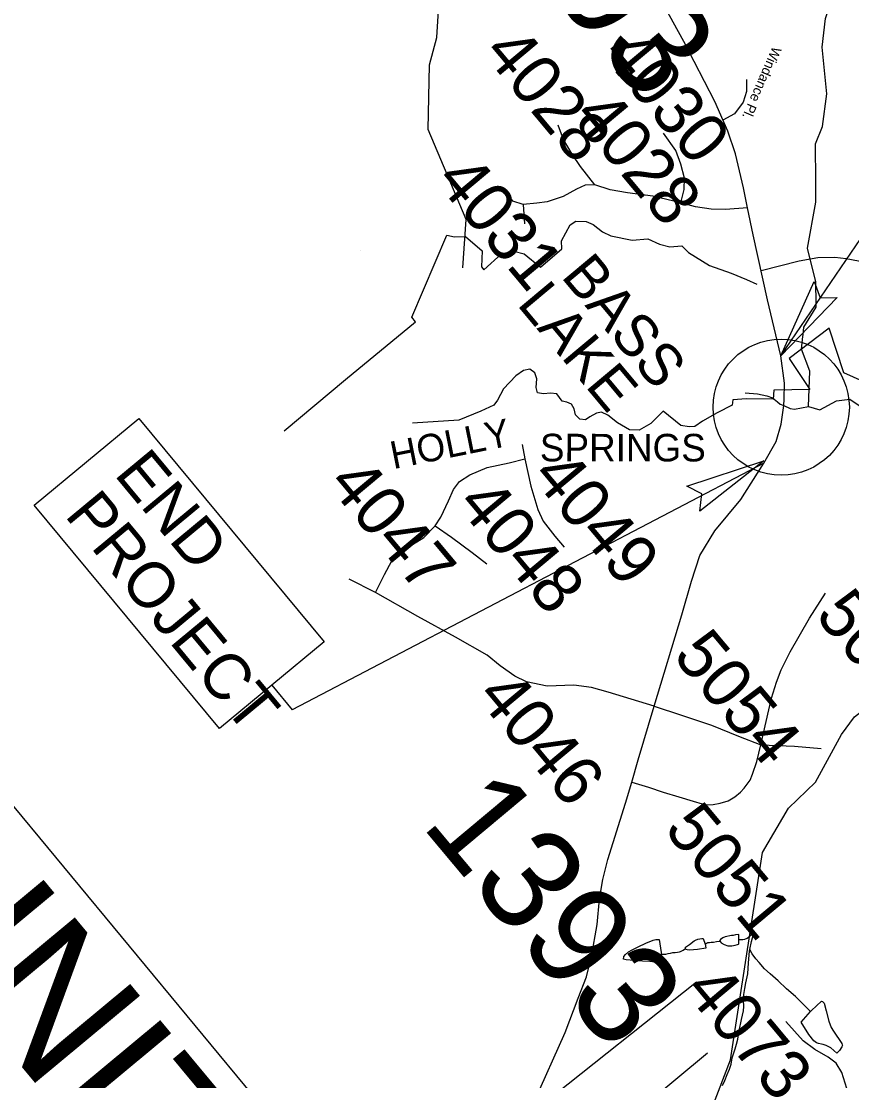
# Model space of a CAD drawing. Extents: x 2054826 to 2060231, y 685508 to 690809.
# Drawn here: x 2058521.5 to 2058702.3, y 689444.4 to 689675 of the extents above; entities that cross this region are included whole.
import ezdxf

# ---------------------------------------------------------------- set-up
doc = ezdxf.new("R2010")
doc.units = 0
for name, color, linetype in [('Old_Level_10', 7, 'Continuous'), ('Old_Level_11', 7, 'Continuous'), ('Old_Level_19', 7, 'Continuous'), ('Old_Level_21', 7, 'Continuous'), ('Old_Level_32', 7, 'Continuous'), ('Old_Level_35', 7, 'Continuous'), ('Old_Level_48', 7, 'Continuous'), ('Old_Level_49', 7, 'Continuous'), ('Old_Level_59', 7, 'Continuous'), ('Old_Level_62', 7, 'Continuous'), ('Old_Level_8', 7, 'Continuous'), ('Prop Dimension', 7, 'Continuous'), ('Prop Horizontal Alignment Station Label', 7, 'Continuous'), ('Typical Terminator CELL', 7, 'Continuous')]:
    doc.layers.add(name, color=color, linetype=linetype)

msp = doc.modelspace()

# ---------------------------------------------------------------- linework, layer by layer
at = {"layer": 'Old_Level_21'}
for p, q in [((2058396.35, 689652.92), (2058754.65, 689220.85)), ((2058595.44, 689625.05), (2058595.44, 689625.05))]:
    msp.add_line(p, q, dxfattribs=at)
msp.add_circle((2058686.91, 689590.96), 14.82, dxfattribs=at)
at = {"layer": 'Old_Level_32'}
for p, q in [((2058630.75, 689635.06), (2058631.05, 689630.83)), ((2058630.52, 689582.85), (2058631.16, 689579.71)), ((2058598.67, 689550.6), (2058592.93, 689553.55))]:
    msp.add_line(p, q, dxfattribs=at)
for points in [[(2058679.59, 689634.33), (2058678.7, 689638.67), (2058676.93, 689646.07), (2058675.26, 689651.03), (2058672.43, 689657.49), (2058665.7, 689670.57), (2058655.97, 689688.24), (2058649.78, 689699.24), (2058645.72, 689707.22), (2058642.52, 689716.04), (2058640.32, 689723.55), (2058638.82, 689731.26), (2058636.85, 689748.06), (2058636.51, 689755.34), (2058636.4, 689760.19), (2058636.96, 689764.8), (2058637.85, 689768.69), (2058640.76, 689779.82), (2058643.98, 689790.93), (2058649.46, 689810.49), (2058652.07, 689818.96), (2058653.3, 689824.33)], [(2058646.33, 689639.34), (2058643.26, 689643.35), (2058641.44, 689646.01), (2058639.57, 689649.19), (2058638.36, 689652.32)], [(2058665.05, 689635.47), (2058665.78, 689638.36), (2058665.86, 689640.83), (2058665.07, 689643.85), (2058663.96, 689646.86), (2058661.31, 689650.59)], [(2058646.33, 689639.34), (2058644.23, 689639.25), (2058642.35, 689638.41), (2058639.46, 689636.8), (2058636.01, 689635.68), (2058633.73, 689635.35), (2058630.75, 689635.06)], [(2058665.05, 689635.47), (2058658.99, 689636.86), (2058653.49, 689637.64), (2058649.72, 689638.29), (2058646.33, 689639.34)], [(2058630.75, 689635.06), (2058628.49, 689635.81), (2058627.08, 689638.01)], [(2058679.59, 689634.33), (2058674.82, 689633.95), (2058671.66, 689634.05), (2058668.25, 689634.6), (2058665.05, 689635.47)], [(2058687.48, 689591.3), (2058687.58, 689592.69), (2058687.6, 689596.18), (2058686.83, 689602.17), (2058683.91, 689614.31), (2058680.84, 689628.49), (2058679.59, 689634.33)], [(2058659.29, 689525.92), (2058665.27, 689545.77), (2058667.38, 689553.08), (2058669.23, 689558.71), (2058672.47, 689564.03), (2058678.09, 689570.87), (2058683.13, 689578.76), (2058685.84, 689583.47), (2058686.9, 689587.23), (2058687.48, 689591.3)], [(2058611.62, 689565.14), (2058612.87, 689567.06), (2058614.5, 689570.59), (2058615.62, 689573.07), (2058616.94, 689574.81), (2058619.17, 689576.27), (2058622.95, 689577.83), (2058627.7, 689578.86), (2058631.16, 689579.71)], [(2058631.16, 689579.71), (2058632.42, 689573.78), (2058633.98, 689568.67), (2058635.1, 689566.12), (2058637.63, 689562.86), (2058639.67, 689560.46)], [(2058598.67, 689550.6), (2058600.59, 689554.55), (2058602.19, 689557.49), (2058603.86, 689559.25), (2058606.72, 689561.11), (2058609.17, 689562.62), (2058611.62, 689565.14)], [(2058611.62, 689565.14), (2058615.17, 689562.67), (2058619.7, 689559.3), (2058622.89, 689556.88)], [(2058659.29, 689525.92), (2058649.23, 689528.94), (2058645.61, 689529.92), (2058641.76, 689530.44), (2058635.95, 689530.27), (2058631.51, 689531.17), (2058628.98, 689532.4), (2058625.76, 689534.65), (2058622.91, 689537.01), (2058616.05, 689540.9), (2058607.86, 689545.42), (2058598.67, 689550.6)], [(2058682.48, 689517.51), (2058684.8, 689527.64), (2058685.88, 689531.08), (2058686.92, 689533.78), (2058688.89, 689537.75), (2058693.08, 689545.07), (2058696.52, 689550.48)], [(2058654.38, 689509.38), (2058655.78, 689514.23), (2058659.29, 689525.92)], [(2058659.29, 689525.92), (2058665.22, 689523.93), (2058671.73, 689521.79), (2058677.65, 689519.33), (2058682.48, 689517.51)], [(2058654.38, 689509.38), (2058658.04, 689508.26), (2058661.24, 689507.2), (2058664.62, 689506.18), (2058667.76, 689505.19), (2058669.74, 689504.6), (2058670.78, 689504.41), (2058672.11, 689504.5), (2058673.6, 689504.75), (2058675.36, 689505.28), (2058676.79, 689506.15), (2058678.06, 689507.17), (2058678.83, 689508.04), (2058680.12, 689509.81), (2058680.63, 689511.08), (2058681.61, 689513.87), (2058682.48, 689517.51)], [(2058623.47, 689405.45), (2058622.51, 689407.72), (2058622.25, 689409.71), (2058622.42, 689412.39), (2058623.56, 689415.82), (2058626.32, 689422.6), (2058633.19, 689439.78), (2058639.88, 689454.86), (2058642.73, 689462.33), (2058644.57, 689467.01), (2058645.65, 689471.4), (2058646.84, 689478.34), (2058647.37, 689483.86), (2058648.12, 689488.16), (2058649.2, 689492.55), (2058653.05, 689504.79), (2058654.38, 689509.38)], [(2058701.16, 689442.68), (2058700.09, 689446.13), (2058698.89, 689448.2), (2058697.15, 689449.48), (2058694.2, 689451.16), (2058691.65, 689453.09), (2058687.93, 689457.27)]]:
    msp.add_lwpolyline(points, dxfattribs=at)
at = {"layer": 'Old_Level_35'}
msp.add_line((2058668.48, 689465.84), (2058632.05, 689436.93), dxfattribs=at)
for points in [[(2058679.34, 689662.29), (2058679.38, 689659.65), (2058678.63, 689657.36), (2058676.76, 689654.8), (2058674.21, 689653.41)], [(2058729.82, 689625.46), (2058728.17, 689624.55), (2058726.18, 689623.62), (2058723.07, 689622.72), (2058716.12, 689621.83), (2058711.64, 689621.42), (2058708.29, 689621.9), (2058701.07, 689623.22), (2058698.61, 689623.55), (2058694.9, 689623.44), (2058690.83, 689622.76), (2058682.54, 689620.63)], [(2058682.48, 689517.51), (2058689.81, 689517.17), (2058695.62, 689516.65)], [(2058631.3, 689435.05), (2058637.84, 689432.16), (2058641.06, 689430.76), (2058643.15, 689430.28), (2058645.17, 689430.88), (2058649.86, 689434.93), (2058657.5, 689439.33), (2058670.89, 689450.41)]]:
    msp.add_lwpolyline(points, dxfattribs=at)
at = {"layer": 'Old_Level_48'}
for points in [[(2058578.77, 689585.78), (2058592.13, 689596.95), (2058607.35, 689609.55), (2058606.54, 689610.52), (2058614.12, 689628.42), (2058615.81, 689628.05), (2058618.21, 689628.13), (2058621.83, 689624.96), (2058621.67, 689621.53), (2058622.22, 689620.88), (2058626.05, 689624.36), (2058628.72, 689624.95), (2058630.99, 689624.37), (2058634.55, 689621.43), (2058639.15, 689625.41), (2058639.08, 689627.14), (2058640.97, 689630.65), (2058642.24, 689631.43), (2058644.48, 689631.38), (2058645.99, 689630.72), (2058648.02, 689629.12), (2058649.82, 689628.28), (2058654.46, 689627.34), (2058657.91, 689627.61), (2058660.42, 689626.41), (2058662.69, 689625.83), (2058665.26, 689626.05), (2058666.71, 689624.65), (2058671.28, 689621.81), (2058676, 689620.12), (2058679.33, 689618.77), (2058681.63, 689617.77)], [(2058697.34, 689608.16), (2058688.67, 689601.56), (2058693.17, 689594.79), (2058685.3, 689594.64), (2058685.13, 689592.7), (2058679.35, 689592.8), (2058676.36, 689592.56)], [(2058711.73, 689593.42), (2058700.51, 689598.47), (2058697.34, 689608.16)], [(2058676.36, 689592.56), (2058676.26, 689591.37), (2058672.96, 689589.72), (2058669.81, 689587.9), (2058668.13, 689586.78), (2058666.85, 689586.67), (2058665.08, 689586.98), (2058661.23, 689590.09), (2058658.52, 689587.41), (2058656, 689585.99), (2058653.91, 689586.03), (2058651.27, 689587.54), (2058649.17, 689589.22), (2058647.8, 689589.87), (2058646.74, 689589.67), (2058645.24, 689588.83), (2058644.3, 689588.24), (2058643.12, 689588.34), (2058642.15, 689589.33), (2058641.89, 689590.62), (2058641.31, 689591.65), (2058640.3, 689592.04), (2058639.27, 689592.28), (2058638.06, 689593.89), (2058636.73, 689594.01), (2058635.21, 689593.84), (2058633.89, 689594.11), (2058633.61, 689595.26), (2058633.71, 689597.13), (2058633.3, 689598.44), (2058632.24, 689599.21), (2058630.8, 689598.96), (2058629.19, 689597.75), (2058626.47, 689594.93), (2058625.2, 689592.49), (2058624.35, 689591.37), (2058621.55, 689590.12), (2058616.73, 689588.16), (2058606.7, 689587.48)]]:
    msp.add_lwpolyline(points, dxfattribs=at)
at = {"layer": 'Old_Level_49'}
for points in [[(2058578.77, 689585.78), (2058592.13, 689596.95), (2058607.35, 689609.55), (2058606.54, 689610.52), (2058614.12, 689628.42), (2058615.81, 689628.05), (2058618.21, 689628.13), (2058621.83, 689624.96), (2058621.67, 689621.53), (2058622.22, 689620.88), (2058626.05, 689624.36), (2058628.72, 689624.95), (2058630.99, 689624.37), (2058634.55, 689621.43), (2058639.15, 689625.41), (2058639.08, 689627.14), (2058640.97, 689630.65), (2058642.24, 689631.43), (2058644.48, 689631.38), (2058645.99, 689630.72), (2058648.02, 689629.12), (2058649.82, 689628.28), (2058654.46, 689627.34), (2058657.91, 689627.61), (2058660.42, 689626.41), (2058662.69, 689625.83), (2058665.26, 689626.05), (2058666.71, 689624.65), (2058671.28, 689621.81), (2058676, 689620.12), (2058679.33, 689618.77), (2058681.63, 689617.77)], [(2058711.73, 689593.42), (2058700.51, 689598.47), (2058697.34, 689608.16)], [(2058676.36, 689592.56), (2058676.26, 689591.37), (2058672.96, 689589.72), (2058669.81, 689587.9), (2058668.13, 689586.78), (2058666.85, 689586.67), (2058665.08, 689586.98), (2058661.23, 689590.09), (2058658.52, 689587.41), (2058656, 689585.99), (2058653.91, 689586.03), (2058651.27, 689587.54), (2058649.17, 689589.22), (2058647.8, 689589.87), (2058646.74, 689589.67), (2058645.24, 689588.83), (2058644.3, 689588.24), (2058643.12, 689588.34), (2058642.15, 689589.33), (2058641.89, 689590.62), (2058641.31, 689591.65), (2058640.3, 689592.04), (2058639.27, 689592.28), (2058638.06, 689593.89), (2058636.73, 689594.01), (2058635.21, 689593.84), (2058633.89, 689594.11), (2058633.61, 689595.26), (2058633.71, 689597.13), (2058633.3, 689598.44), (2058632.24, 689599.21), (2058630.8, 689598.96), (2058629.19, 689597.75), (2058626.47, 689594.93), (2058625.2, 689592.49), (2058624.35, 689591.37), (2058621.55, 689590.12), (2058616.73, 689588.16), (2058606.7, 689587.48)]]:
    msp.add_lwpolyline(points, dxfattribs=at)
at = {"layer": 'Old_Level_59'}
msp.add_line((2058691.61, 689606.33), (2058691.65, 689606.72), dxfattribs=at)
for points in [[(2058694.42, 689639.99), (2058694.37, 689648.3), (2058695.89, 689652.02), (2058696.85, 689659.18), (2058695.83, 689669.3), (2058696.54, 689675.57), (2058699.69, 689685.28), (2058699.88, 689689.3), (2058691.88, 689705.23), (2058678.93, 689720.14)], [(2058617.62, 689621.3), (2058618.34, 689631.82), (2058610.12, 689651.43), (2058610.36, 689665.44), (2058612.01, 689671.39), (2058612.82, 689685.54), (2058610.66, 689695.39), (2058612.43, 689702.89), (2058611.64, 689710.31)], [(2058694.5, 689613.56), (2058694.42, 689618.25), (2058692.63, 689625.6), (2058694.44, 689635.6), (2058694.42, 689639.99)], [(2058691.65, 689606.72), (2058691.84, 689608.35), (2058694.51, 689612.7), (2058694.5, 689613.56)], [(2058692.83, 689591.12), (2058693.11, 689598.77), (2058691.29, 689603.6), (2058691.61, 689606.33)], [(2058679.1, 689594.08), (2058681.75, 689593.84), (2058683.81, 689593.41), (2058684.99, 689592.98), (2058686.11, 689592.13), (2058686.7, 689591.61), (2058687.48, 689591.3), (2058688.88, 689590.65), (2058689.8, 689590.54), (2058692.83, 689591.12)], [(2058692.83, 689591.12), (2058695.33, 689590.38), (2058698.93, 689592.37), (2058701.83, 689592.67), (2058706.54, 689589.53), (2058713.31, 689581.09), (2058716.37, 689572), (2058719.54, 689566.18), (2058727.39, 689557.58), (2058734.93, 689553.63)], [(2058677.76, 689461.15), (2058682.85, 689494.02), (2058688.49, 689503.69), (2058694.36, 689509.32), (2058700.05, 689519.76), (2058702.88, 689523.56), (2058715.07, 689533.08), (2058721.32, 689535.85), (2058725.72, 689540.58), (2058728.44, 689545.03), (2058734.87, 689552.52), (2058734.93, 689553.63)], [(2058657.45, 689394.18), (2058665.56, 689408.08), (2058668.72, 689413.18), (2058670.84, 689419.9), (2058671.54, 689426.18), (2058670.65, 689435.3), (2058675.87, 689448.9), (2058677.76, 689461.15)]]:
    msp.add_lwpolyline(points, dxfattribs=at)
at = {"layer": 'Old_Level_62'}
for points in [[(2058666.07, 689473.13), (2058666.08, 689473.41), (2058666.92, 689474.03), (2058667.96, 689474.81), (2058668.26, 689474.97), (2058668.78, 689475.15), (2058669.62, 689475.36), (2058669.9, 689475.34), (2058670.35, 689474.1)], [(2058677.72, 689475.11), (2058677.72, 689476.22), (2058676.98, 689476.1), (2058676.47, 689476), (2058676.08, 689475.95), (2058674.68, 689475.7), (2058674.2, 689475.46), (2058673.71, 689475.14), (2058673.5, 689474.78)], [(2058677.72, 689475.11), (2058678.14, 689475.13), (2058678.55, 689475.13), (2058679.01, 689475.19), (2058679.5, 689475.42), (2058680.09, 689475.83), (2058680.96, 689476.81)], [(2058680.07, 689472.93), (2058680.45, 689474.68), (2058680.94, 689476.54), (2058680.96, 689476.81)], [(2058660.79, 689471.93), (2058661.08, 689469.96), (2058658.35, 689470.3), (2058656.74, 689470.39), (2058653.16, 689470.7), (2058652.57, 689470.81), (2058652.67, 689471.39), (2058653.03, 689471.87), (2058653.68, 689472.41), (2058654.51, 689472.85), (2058655.76, 689473.48), (2058657.45, 689474.29), (2058659.06, 689474.99), (2058659.64, 689475.12), (2058660.05, 689475.13), (2058660.34, 689475.11), (2058660.77, 689472.26), (2058660.79, 689471.93)], [(2058660.79, 689471.93), (2058661.07, 689471.9), (2058661.33, 689471.89), (2058661.8, 689471.94), (2058662.28, 689472.08), (2058662.79, 689472.17), (2058663.31, 689472.27), (2058663.87, 689472.31), (2058664.32, 689472.36), (2058664.79, 689472.42), (2058664.99, 689472.49), (2058665.56, 689472.81), (2058666.07, 689473.13)], [(2058670.35, 689474.1), (2058670.46, 689473.76), (2058670.54, 689473.25), (2058668.67, 689472.96), (2058666.95, 689472.78), (2058666.41, 689472.83), (2058666.14, 689472.93), (2058666.07, 689473.13)], [(2058670.35, 689474.1), (2058670.79, 689474.37), (2058670.97, 689474.45), (2058671.3, 689474.47), (2058671.67, 689474.53), (2058672.18, 689474.54), (2058672.84, 689474.66), (2058673.5, 689474.78)], [(2058673.5, 689474.78), (2058673.59, 689474.69), (2058673.83, 689474.39), (2058674.48, 689474.01), (2058675.3, 689473.75), (2058676.17, 689473.73), (2058676.92, 689473.84), (2058677.4, 689473.99), (2058677.58, 689474.07), (2058677.68, 689474.16), (2058677.72, 689475.11)], [(2058674.11, 689443.33), (2058674.63, 689444.44), (2058675.16, 689445.73), (2058675.68, 689446.92), (2058676, 689447.96), (2058676.26, 689449.36), (2058676.52, 689450.26), (2058676.89, 689451.33), (2058677.17, 689452.33), (2058677.45, 689453.41), (2058677.79, 689455.22), (2058678.27, 689457.67), (2058678.71, 689459.58), (2058678.8, 689460.5), (2058678.68, 689461.93), (2058678.8, 689463.12), (2058678.96, 689464.44), (2058679.2, 689465.67), (2058679.61, 689467.62), (2058679.8, 689470), (2058680.04, 689472.56), (2058680.07, 689472.93)], [(2058693.27, 689459.41), (2058692.86, 689459.91), (2058691.33, 689461.43), (2058690.01, 689462.69), (2058688.08, 689464.39), (2058686.21, 689466.11), (2058684.5, 689467.65), (2058683.3, 689468.76), (2058682.13, 689470.07), (2058681.42, 689470.91), (2058680.58, 689472.01), (2058680.07, 689472.93)], [(2058693.27, 689459.41), (2058693.48, 689459.66), (2058695.7, 689461.69), (2058695.92, 689461.63), (2058696.26, 689461.22), (2058696.67, 689459.62), (2058697.3, 689457.35), (2058697.81, 689455.93), (2058698.26, 689455.19), (2058700.1, 689452.5), (2058700.18, 689452.21), (2058700.24, 689452.03), (2058700.13, 689451.76), (2058699.6, 689450.98), (2058699.15, 689450.5), (2058698.99, 689450.38), (2058697.71, 689451.5), (2058696.66, 689452.06), (2058696.07, 689452.25), (2058695.65, 689452.34), (2058695.03, 689452.48), (2058694.58, 689452.61), (2058694.32, 689452.82), (2058694.02, 689453.06), (2058692.93, 689454.47), (2058691.23, 689457.1), (2058693.27, 689459.41)]]:
    msp.add_lwpolyline(points, dxfattribs=at)
at = {"layer": 'Prop Dimension'}
for p, q in [((2058686.83, 689602.11), (2058733.22, 689670.33)), ((2058524.38, 689569.6), (2058547.14, 689588.47)), ((2058547.14, 689588.47), (2058587.44, 689539.88)), ((2058683.13, 689578.76), (2058580.48, 689525.11)), ((2058564.68, 689521.01), (2058524.38, 689569.6)), ((2058587.44, 689539.88), (2058564.68, 689521.01)), ((2058576.06, 689530.44), (2058580.48, 689525.11))]:
    msp.add_line(p, q, dxfattribs=at)
at = {"layer": 'Typical Terminator CELL'}
for points in [[(2058699.07, 689614.82), (2058686.8, 689602.14), (2058694.09, 689618.33), (2058695.4, 689614.75)], [(2058666.37, 689573.74), (2058683.12, 689579.32), (2058669.17, 689568.33), (2058669.66, 689572.1)]]:
    msp.add_lwpolyline(points, close=True, dxfattribs=at)

# ---------------------------------------------------------------- texts
at = {"layer": 'Old_Level_10'}
msp.add_text('Windance Pl.', height=2.1325, rotation=246.4451, dxfattribs=at).set_placement((2058685.07, 689669.6))
at = {"layer": 'Old_Level_11'}
msp.add_text('VICINITY MAP', height=29.6875, rotation=309.7424, dxfattribs=at).set_placement((2058458.94, 689522.81))
at = {"layer": 'Old_Level_19'}
for s, rotation, p in [('HOLLY', 11.4095, (2058602.52, 689577.46)), ('SPRINGS', 359.9663, (2058634.4, 689579.17))]:
    msp.add_text(s, height=5.998, rotation=rotation, dxfattribs=at).set_placement(p)
at = {"layer": 'Old_Level_21'}
for s, p in [('BASS', (2058638.81, 689619.38)), ('LAKE', (2058629.23, 689613.33))]:
    msp.add_text(s, height=9.163, rotation=309.9093, dxfattribs=at).set_placement(p)
at = {"layer": 'Old_Level_8'}
for s, height, p in [('1393', 21.964, (2058615.48, 689706.71)), ('4028', 10.796, (2058621.77, 689668.01)), ('4030', 10.796, (2058647.62, 689667.67)), ('4028', 10.796, (2058641.38, 689654.23)), ('4031', 10.796, (2058611.41, 689640.2)), ('4047', 10.796, (2058587.94, 689574.18)), ('4049', 10.796, (2058632.31, 689575.86)), ('4048', 10.796, (2058616.03, 689569.74)), ('5051', 10.796, (2058694.04, 689545.58)), ('5054', 10.796, (2058663.09, 689536.73)), ('4046', 10.796, (2058620.33, 689527.93)), ('1393', 21.964, (2058608.34, 689500.06)), ('5051', 10.796, (2058661.18, 689499)), ('4073', 10.796, (2058665.56, 689463.91))]:
    msp.add_text(s, height=height, rotation=309.9093, dxfattribs=at).set_placement(p)
at = {"layer": 'Prop Horizontal Alignment Station Label'}
for s, p in [('END', (2058541.58, 689576.31)), ('PROJECT', (2058530.8, 689567.38))]:
    msp.add_text(s, height=10, rotation=309.6672, dxfattribs=at).set_placement(p)

doc.saveas('drawing.dxf')
